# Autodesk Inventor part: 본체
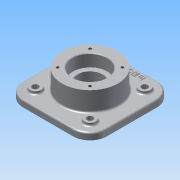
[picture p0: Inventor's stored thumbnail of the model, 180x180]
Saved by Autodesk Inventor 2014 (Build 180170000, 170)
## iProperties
Created: 2015-09
Part Number: 본체
Material: 알루미늄 6061
Document SubType Name: Modeling
Designer: study
Density: 2.71 g/cm^3
Appearance: 알루미늄 - 평지
Mass: 1464.68 g
Surface Area: 800.934 cm^2
Volume: 540.471 cm^3
Author: study
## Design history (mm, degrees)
sketch "스케치1"
  geometry: L1 (-75, 75)-(75, 75); L2 (75, 75)-(75, -75); L3 (75, -75)-(-75, -75); L4 (-75, -75)-(-75, 75); L5 (-75, 75)-(75, -75); L6 (75, 75)-(-75, -75); 1 further point
  constraints: 12 end point, 2 midpoint, 2 parallel, 1 horizontal, 1 perpendicular
  dimensions: "d0" = 150 distance of L1.start L1.end; "d1" = 150 distance of L1.end L2.end
extrude "돌출1" new body sketch "스케치1" distance "d2" = 12; taper "d3" = 0 deg
node "작업 평면1"
sketch "스케치3"
  geometry: C1 r 50 at (0, 0); 1 further point
  constraints: 1 centre point, 1 coincident
  dimensions: "d5" = 100 diameter of C1
extrude "돌출2" join sketch "스케치3" distance "d6" = 70; taper "d7" = 0 deg
sketch "스케치4"
  geometry: C1 r 50 at (0, 0) reference
hole "구멍1" sketch "스케치4" at (0, 0) diameter "d8" = 45; stored, may be unused: countersink angle "d12" = 90 deg, drill point angle "d14" = 0 deg; dims "d9" = 6, "d10" = 62, "d11" = 22, "d13" = 48
sketch "스케치5"
  geometry: C1 r 50 at (0, 0) reference
hole "구멍2" sketch "스케치5" at (0, 0) diameter "d15" = 45; stored, may be unused: countersink angle "d19" = 90 deg, drill point angle "d21" = 0 deg; dims "d16" = 6, "d17" = 62, "d18" = 22, "d20" = 48
sketch "스케치6"
  geometry: L1 (0, 41)-(0, 0); C1 r 31 at (0, 0) reference; C2 r 50 at (0, 0) reference; A1 r 41 centre (0, 0) between (0, 41) and (-28.991, 28.991)
  constraints: 2 end point, 2 point on circle, 1 centre point, 1 coincident, 1 vertical
  dimensions: "d22" = 82 diameter of A1; "d23" = 45 deg dimension on C1.centre A1.end L1.start
hole "구멍3" sketch "스케치6" at (-28.991, 28.991) diameter "d24" = 4.917; stored, may be unused: countersink angle "d28" = 90 deg, drill point angle "d30" = 118 deg; dims "d25" = 10, "d26" = 62, "d27" = 22, "d29" = 13
node "작업 평면2"
fillet "모깎기1" dims "d34" = 30
sketch "스케치7"
  geometry: L1 (-49, 49)-(49, 49); L2 (49, 49)-(49, -49); L3 (49, -49)-(-49, -49); L4 (-49, -49)-(-49, 49); L5 (-49, 49)-(49, -49); L6 (49, 49)-(-49, -49); C1 r 50 at (0, 0) reference; C2 r 10 at (-49, 49); C3 r 10 at (-49, -49); C4 r 10 at (49, -49); C5 r 10 at (49, 49); C6 r 5.5 at (-49, -49); C7 r 5.5 at (-49, 49); C8 r 5.5 at (49, 49); C9 r 5.5 at (49, -49); 1 further point
  constraints: 12 end point, 9 coincident, 8 centre point, 6 equal radius, 2 midpoint, 2 parallel, 1 horizontal, 1 perpendicular
  dimensions: "d35" = 98 distance of L1.start L1.end; "d36" = 98 distance of L1.end L2.end; "d37" = 20 diameter of C2; "d38" = 11 diameter of C7
extrude "돌출3" join sketch "스케치7" distance "d39" = 5; taper "d40" = 0 deg
extrude "돌출4" cut sketch "스케치7" distance "d41" = 31.25; taper "d42" = 0 deg
sketch "스케치8"
  geometry: C1 r 50 at (0, 0) reference; 1 further point
  constraints: 1 vertical alignment, 1 other
  dimensions: "d43" = 65 distance of C1.centre point (0, 65)
feature "엠보싱1" sketch "스케치8" dims "d44" = 1, "d45" = 0
fillet "모깎기2" dims "d46" = 0.3, "d47" = 3
chamfer "모따기1" distance "d48" = 1; stored, may be unused: second distance "d49" = 2, angle "d50" = 45 deg
node "솔리드1"
pattern_circular "원형 패턴1" dims angle "d32" = 360 deg
mirror "대칭1"
other parameters: "d4" = 23
